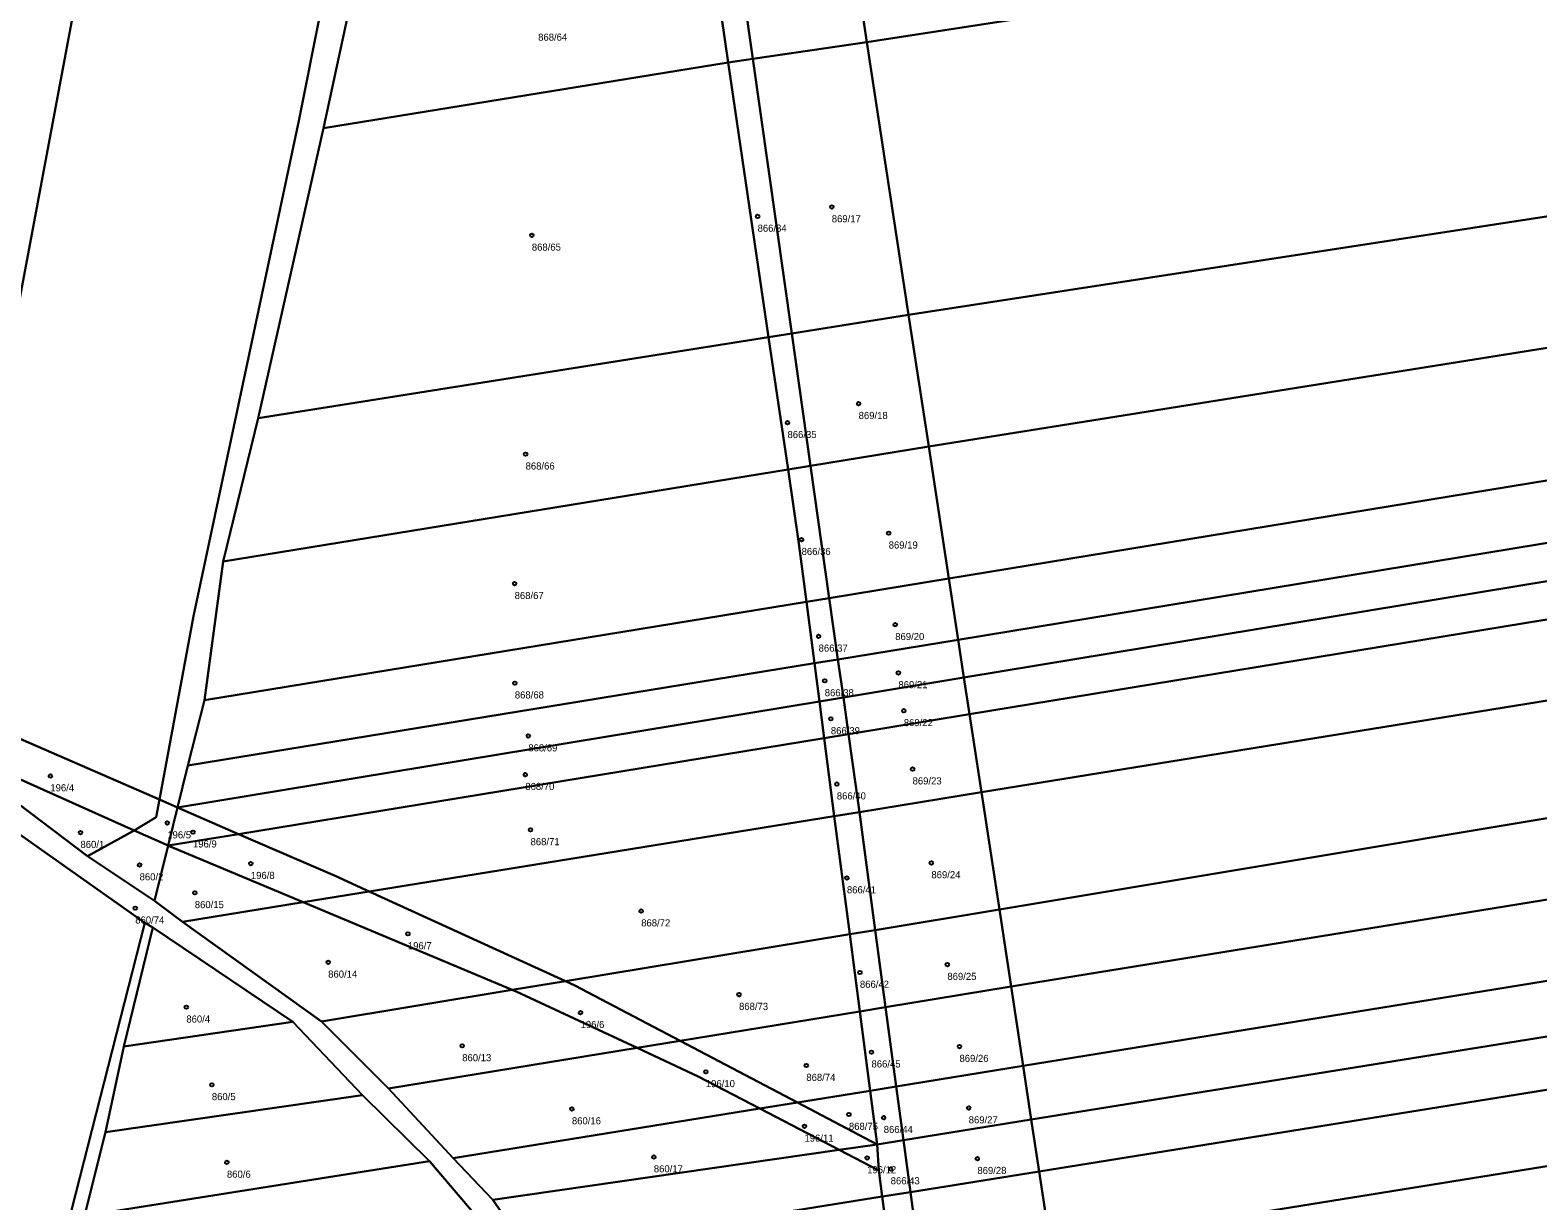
# Model space of a CAD drawing. Extents: x -587171 to -555306, y -1167727 to -1074732.
# Drawn here: x -584940 to -584727.9, y -1165439.3 to -1165274.5 of the extents above; entities that cross this region are included whole.
import ezdxf

# ---------------------------------------------------------------- set-up
doc = ezdxf.new("R2010")
doc.units = 0
doc.layers.add('Definiční body', color=7, linetype='Continuous')
doc.layers.add('Polygon parcely', color=7, linetype='Continuous')

msp = doc.modelspace()

# ---------------------------------------------------------------- linework, layer by layer
at = {"layer": 'Definiční body'}
for centre in [(-584827.22, -1165299.43), (-584837.66, -1165300.76), (-584869.43, -1165303.42), (-584823.44, -1165327.11), (-584833.45, -1165329.79), (-584870.31, -1165334.22), (-584831.47, -1165346.25), (-584819.21, -1165345.34), (-584871.85, -1165352.45), (-584818.29, -1165358.22), (-584829.07, -1165359.85), (-584828.21, -1165366.12), (-584817.84, -1165365), (-584871.82, -1165366.44), (-584817.08, -1165370.33), (-584827.35, -1165371.47), (-584869.93, -1165373.89), (-584815.85, -1165378.54), (-584937.19, -1165379.5), (-584870.35, -1165379.32), (-584826.51, -1165380.65), (-584920.73, -1165386.13), (-584869.61, -1165387.09), (-584932.95, -1165387.48), (-584917.12, -1165387.41), (-584924.63, -1165392.04), (-584908.97, -1165391.84), (-584813.2, -1165391.74), (-584825.09, -1165393.86), (-584916.86, -1165395.95), (-584925.24, -1165398.11), (-584854.04, -1165398.52), (-584886.87, -1165401.73), (-584898.09, -1165405.73), (-584810.95, -1165406.05), (-584823.26, -1165407.16), (-584840.27, -1165410.27), (-584918.05, -1165412.05), (-584862.57, -1165412.82), (-584879.23, -1165417.49), (-584821.63, -1165418.37), (-584809.25, -1165417.59), (-584844.94, -1165421.14), (-584830.8, -1165420.26), (-584914.46, -1165422.97), (-584863.79, -1165426.37), (-584824.81, -1165427.15), (-584819.91, -1165427.59), (-584807.95, -1165426.24), (-584831.06, -1165428.81), (-584912.34, -1165433.89), (-584852.26, -1165433.13), (-584822.24, -1165433.26), (-584806.73, -1165433.36), (-584818.93, -1165434.81)]:
    msp.add_circle(centre, 0.25, dxfattribs=at)
at = {"layer": 'Polygon parcely'}
for points in [[(-584893.49, -1165051.51), (-584911.55, -1165050.01), (-584941.09, -1165219.48), (-584966.57, -1165363.39), (-584952.29, -1165369.6), (-584925.66, -1165227.85), (-584895.33, -1165063.56)], [(-584902.21, -1165287.33), (-584883.81, -1165195.03), (-584866.02, -1165107.69), (-584871.7, -1165066.81), (-584877.29, -1165065.98), (-584895.33, -1165063.56), (-584925.66, -1165227.85), (-584952.29, -1165369.6), (-584921.83, -1165382.84), (-584917.06, -1165357.03)], [(-584891.42, -1165256.89), (-584889.07, -1165245.63), (-584885.14, -1165223.11), (-584881.74, -1165199.81), (-584875.97, -1165175.55), (-584870.48, -1165151.46), (-584864.44, -1165119), (-584865.05, -1165114.66), (-584866.02, -1165107.69), (-584883.81, -1165195.03), (-584902.21, -1165287.33), (-584917.06, -1165357.03), (-584921.83, -1165382.84), (-584919.3, -1165383.94), (-584917.84, -1165378.02), (-584915.49, -1165368.85), (-584912.89, -1165349.33), (-584907.92, -1165329.17), (-584898.75, -1165288.32), (-584894.3, -1165267.63)], [(-584351.89, -1165200.16), (-584365.79, -1165182.86), (-584489.27, -1165203.63), (-584611.49, -1165224.19), (-584718.07, -1165240.31), (-584825.25, -1165256.52), (-584822.27, -1165276.26), (-584720.86, -1165260.58), (-584619.2, -1165244.86), (-584486.44, -1165222.66)], [(-584323.29, -1165235.74), (-584351.89, -1165200.16), (-584486.44, -1165222.66), (-584619.2, -1165244.86), (-584720.86, -1165260.58), (-584822.27, -1165276.26), (-584816.4, -1165314.6), (-584703.23, -1165297.14), (-584589.9, -1165279.66), (-584445.07, -1165255.56)], [(-584310.41, -1165251.76), (-584323.29, -1165235.74), (-584445.07, -1165255.56), (-584589.9, -1165279.66), (-584703.23, -1165297.14), (-584816.4, -1165314.6), (-584813.57, -1165333.16), (-584703.91, -1165315.64), (-584594.47, -1165298.16), (-584433.81, -1165271.54)], [(-584297.99, -1165267.22), (-584310.41, -1165251.76), (-584433.81, -1165271.54), (-584594.47, -1165298.16), (-584703.91, -1165315.64), (-584813.57, -1165333.16), (-584810.74, -1165351.73), (-584697.98, -1165333.21), (-584585.84, -1165314.8), (-584423.32, -1165288.16)], [(-584822.27, -1165276.26), (-584825.25, -1165256.52), (-584841.12, -1165259.07), (-584838.35, -1165278.56)], [(-584841.78, -1165279.11), (-584844.63, -1165259.63), (-584894.3, -1165267.63), (-584898.75, -1165288.32)], [(-584841.78, -1165279.11), (-584838.35, -1165278.56), (-584841.12, -1165259.07), (-584844.63, -1165259.63)], [(-584291.06, -1165275.84), (-584297.99, -1165267.22), (-584423.32, -1165288.16), (-584585.84, -1165314.8), (-584697.98, -1165333.21), (-584810.74, -1165351.73), (-584809.43, -1165360.34), (-584694.26, -1165341.41), (-584579.59, -1165322.56), (-584417.2, -1165296.32)], [(-584816.4, -1165314.6), (-584822.27, -1165276.26), (-584838.35, -1165278.56), (-584832.86, -1165317.22)], [(-584287.34, -1165280.47), (-584291.06, -1165275.84), (-584417.2, -1165296.32), (-584579.59, -1165322.56), (-584694.26, -1165341.41), (-584809.43, -1165360.34), (-584808.62, -1165365.66), (-584694.75, -1165346.85), (-584581.15, -1165328.08), (-584416.04, -1165301.57)], [(-584836.12, -1165317.74), (-584832.86, -1165317.22), (-584838.35, -1165278.56), (-584841.78, -1165279.11)], [(-584836.12, -1165317.74), (-584841.78, -1165279.11), (-584898.75, -1165288.32), (-584907.92, -1165329.17)], [(-584283.55, -1165285.11), (-584284.55, -1165283.94), (-584287.34, -1165280.47), (-584416.04, -1165301.57), (-584581.15, -1165328.08), (-584694.75, -1165346.85), (-584808.62, -1165365.66), (-584807.83, -1165370.83), (-584692.25, -1165351.86), (-584577.37, -1165333.01), (-584418.95, -1165307.4)], [(-584274.66, -1165295.49), (-584283.55, -1165285.11), (-584418.95, -1165307.4), (-584577.37, -1165333.01), (-584692.25, -1165351.86), (-584807.83, -1165370.83), (-584806.16, -1165381.79), (-584689.43, -1165362.9), (-584572.61, -1165344), (-584411.37, -1165317.9)], [(-584262.29, -1165309.93), (-584274.66, -1165295.49), (-584411.37, -1165317.9), (-584572.61, -1165344), (-584689.43, -1165362.9), (-584806.16, -1165381.79), (-584803.64, -1165398.31), (-584684.63, -1165378.47), (-584566.14, -1165358.72), (-584403.21, -1165332.77)], [(-584253.65, -1165320.01), (-584262.29, -1165309.93), (-584403.21, -1165332.77), (-584566.14, -1165358.72), (-584684.63, -1165378.47), (-584803.64, -1165398.31), (-584801.99, -1165409.15), (-584685.41, -1165390.24), (-584569.1, -1165371.38), (-584400.01, -1165343.55)], [(-584813.57, -1165333.16), (-584816.4, -1165314.6), (-584832.86, -1165317.22), (-584830.21, -1165335.87)], [(-584833.38, -1165336.39), (-584836.12, -1165317.74), (-584907.92, -1165329.17), (-584912.89, -1165349.33)], [(-584832.86, -1165317.22), (-584836.12, -1165317.74), (-584833.38, -1165336.39), (-584830.21, -1165335.87)], [(-584245.68, -1165329.31), (-584253.65, -1165320.01), (-584400.01, -1165343.55), (-584569.1, -1165371.38), (-584685.41, -1165390.24), (-584801.99, -1165409.15), (-584800.29, -1165420.32), (-584679.97, -1165400.79), (-584559.08, -1165381.16), (-584392.72, -1165353.46)], [(-584240.53, -1165335.32), (-584245.68, -1165329.31), (-584392.72, -1165353.46), (-584559.08, -1165381.16), (-584679.97, -1165400.79), (-584800.29, -1165420.32), (-584799.14, -1165427.86), (-584679.59, -1165408.61), (-584558.94, -1165389.19), (-584384.85, -1165359.88)], [(-584810.74, -1165351.73), (-584813.57, -1165333.16), (-584830.21, -1165335.87), (-584827.57, -1165354.48)], [(-584830.21, -1165335.87), (-584833.38, -1165336.39), (-584831.86, -1165346.79), (-584830.79, -1165355.01), (-584827.57, -1165354.48)], [(-584234.7, -1165342.13), (-584240.53, -1165335.32), (-584384.85, -1165359.88), (-584558.94, -1165389.19), (-584679.59, -1165408.61), (-584799.14, -1165427.86), (-584798.03, -1165435.17), (-584677.37, -1165415.73), (-584556.85, -1165396.31), (-584382.81, -1165367.17)], [(-584830.79, -1165355.01), (-584831.86, -1165346.79), (-584833.38, -1165336.39), (-584912.89, -1165349.33), (-584915.49, -1165368.85)], [(-584225.63, -1165352.72), (-584234.7, -1165342.13), (-584382.81, -1165367.17), (-584556.85, -1165396.31), (-584677.37, -1165415.73), (-584798.03, -1165435.17), (-584796.43, -1165445.7), (-584675.02, -1165426.1), (-584553.98, -1165406.56), (-584379.31, -1165377.66)], [(-584809.43, -1165360.34), (-584810.74, -1165351.73), (-584827.57, -1165354.48), (-584826.35, -1165363.1)], [(-584214.53, -1165366.86), (-584221.82, -1165357.17), (-584225.63, -1165352.72), (-584379.31, -1165377.66), (-584553.98, -1165406.56), (-584675.02, -1165426.1), (-584796.43, -1165445.7), (-584794.03, -1165461.44), (-584670.52, -1165441.54), (-584547.57, -1165421.73), (-584380.19, -1165393.99)], [(-584829.67, -1165363.64), (-584830.79, -1165355.01), (-584915.49, -1165368.85), (-584917.84, -1165378.02)], [(-584829.67, -1165363.64), (-584826.35, -1165363.1), (-584827.57, -1165354.48), (-584830.79, -1165355.01)], [(-584808.62, -1165365.66), (-584809.43, -1165360.34), (-584826.35, -1165363.1), (-584825.59, -1165368.46)], [(-584828.97, -1165369.02), (-584829.67, -1165363.64), (-584917.84, -1165378.02), (-584919.3, -1165383.94)], [(-584825.59, -1165368.46), (-584826.35, -1165363.1), (-584829.67, -1165363.64), (-584828.97, -1165369.02)], [(-584807.83, -1165370.83), (-584808.62, -1165365.66), (-584825.59, -1165368.46), (-584824.86, -1165373.62)], [(-584953.66, -1165379.16), (-584971.92, -1165368.54), (-585005.85, -1165517.15), (-585002.31, -1165515.83), (-584997.11, -1165513.9), (-584991.97, -1165511.88), (-584986.52, -1165509.33), (-584981.47, -1165507.66), (-584976.27, -1165505.29), (-584971.31, -1165503.17), (-584966.14, -1165501.04), (-584961.72, -1165499.08), (-584956.22, -1165496.67), (-584951.29, -1165494.26), (-584947.38, -1165492.07), (-584923.91, -1165400.16)], [(-584922.29, -1165385.31), (-584921.83, -1165382.84), (-584952.29, -1165369.6), (-584953.26, -1165374.68), (-584925.4, -1165387.17)], [(-584828.3, -1165374.18), (-584828.97, -1165369.02), (-584919.3, -1165383.94), (-584910.71, -1165387.68)], [(-584825.59, -1165368.46), (-584828.97, -1165369.02), (-584828.3, -1165374.18), (-584824.86, -1165373.62)], [(-584806.16, -1165381.79), (-584807.83, -1165370.83), (-584824.86, -1165373.62), (-584823.34, -1165384.58)], [(-584826.87, -1165385.15), (-584828.3, -1165374.18), (-584910.71, -1165387.68), (-584897.13, -1165393.58), (-584892.33, -1165395.77)], [(-584826.87, -1165385.15), (-584823.34, -1165384.58), (-584824.86, -1165373.62), (-584828.3, -1165374.18)], [(-584931.98, -1165390.81), (-584925.4, -1165387.17), (-584953.26, -1165374.68)], [(-584920.63, -1165389.3), (-584919.3, -1165383.94), (-584921.83, -1165382.84), (-584922.29, -1165385.31), (-584925.4, -1165387.17)], [(-584803.64, -1165398.31), (-584806.16, -1165381.79), (-584823.34, -1165384.58), (-584821.11, -1165401.19)], [(-584919.3, -1165383.94), (-584920.63, -1165389.3), (-584910.71, -1165387.68)], [(-584823.34, -1165384.58), (-584826.87, -1165385.15), (-584824.7, -1165401.78), (-584821.11, -1165401.19)], [(-584824.7, -1165401.78), (-584826.87, -1165385.15), (-584892.33, -1165395.77), (-584864.69, -1165408.38)], [(-584931.98, -1165390.81), (-584922.55, -1165397.09), (-584920.63, -1165389.3), (-584925.4, -1165387.17)], [(-584901.63, -1165397.28), (-584892.33, -1165395.77), (-584897.13, -1165393.58), (-584910.71, -1165387.68), (-584920.63, -1165389.3), (-584920.32, -1165389.44)], [(-584918.6, -1165400.03), (-584901.63, -1165397.28), (-584920.32, -1165389.44), (-584920.63, -1165389.3), (-584922.55, -1165397.09)], [(-584899.05, -1165414.05), (-584872.2, -1165409.62), (-584901.63, -1165397.28), (-584918.6, -1165400.03)], [(-584892.33, -1165395.77), (-584901.63, -1165397.28), (-584872.2, -1165409.62), (-584864.69, -1165408.38)], [(-584801.99, -1165409.15), (-584803.64, -1165398.31), (-584821.11, -1165401.19), (-584819.65, -1165412.04)], [(-584936.62, -1165457.2), (-584932.39, -1165441.39), (-584929.45, -1165429.65), (-584926.85, -1165417.59), (-584922.77, -1165400.81), (-584923.91, -1165400.16), (-584947.38, -1165492.07), (-584944.94, -1165491.18), (-584939.72, -1165468.93)], [(-584903.08, -1165414.11), (-584922.77, -1165400.81), (-584926.85, -1165417.59)], [(-584823.29, -1165412.64), (-584824.7, -1165401.78), (-584864.69, -1165408.38), (-584863.37, -1165408.98), (-584848.55, -1165416.78)], [(-584821.11, -1165401.19), (-584824.7, -1165401.78), (-584823.29, -1165412.64), (-584819.65, -1165412.04)], [(-584889.6, -1165423.5), (-584854.63, -1165417.78), (-584871.62, -1165409.86), (-584872.2, -1165409.62), (-584899.05, -1165414.05)], [(-584864.69, -1165408.38), (-584872.2, -1165409.62), (-584871.62, -1165409.86), (-584854.63, -1165417.78), (-584848.55, -1165416.78), (-584863.37, -1165408.98)], [(-584800.29, -1165420.32), (-584801.99, -1165409.15), (-584819.65, -1165412.04), (-584818.15, -1165423.21)], [(-584821.83, -1165423.8), (-584818.15, -1165423.21), (-584819.65, -1165412.04), (-584823.29, -1165412.64)], [(-584903.08, -1165414.11), (-584926.85, -1165417.59), (-584929.45, -1165429.65), (-584893.28, -1165424.44)], [(-584821.83, -1165423.8), (-584823.29, -1165412.64), (-584848.55, -1165416.78), (-584832.06, -1165425.45)], [(-584846.02, -1165421.79), (-584837.35, -1165426.31), (-584832.06, -1165425.45), (-584848.55, -1165416.78), (-584854.63, -1165417.78)], [(-584837.35, -1165426.31), (-584846.02, -1165421.79), (-584854.63, -1165417.78), (-584889.6, -1165423.5), (-584880.48, -1165433.28)], [(-584799.14, -1165427.86), (-584800.29, -1165420.32), (-584818.15, -1165423.21), (-584817.14, -1165430.75)], [(-584818.15, -1165423.21), (-584821.83, -1165423.8), (-584820.85, -1165431.35), (-584817.14, -1165430.75)], [(-584883.83, -1165433.73), (-584893.28, -1165424.44), (-584929.45, -1165429.65), (-584932.39, -1165441.39)], [(-584832.06, -1165425.45), (-584820.85, -1165431.35), (-584821.83, -1165423.8)], [(-584874.94, -1165439.14), (-584826.19, -1165432.12), (-584837.35, -1165426.31), (-584880.48, -1165433.28)], [(-584826.19, -1165432.12), (-584820.85, -1165431.35), (-584832.06, -1165425.45), (-584837.35, -1165426.31)], [(-584798.03, -1165435.17), (-584799.14, -1165427.86), (-584817.14, -1165430.75), (-584816.16, -1165438.07)], [(-584820.6, -1165435.03), (-584820.85, -1165431.35), (-584826.19, -1165432.12)], [(-584817.14, -1165430.75), (-584820.85, -1165431.35), (-584820.6, -1165435.03), (-584820.11, -1165438.7), (-584816.16, -1165438.07)], [(-584883.83, -1165433.73), (-584932.39, -1165441.39), (-584936.62, -1165457.2), (-584872.59, -1165446.93)], [(-584869.72, -1165446.64), (-584820.11, -1165438.7), (-584820.6, -1165435.03), (-584826.19, -1165432.12), (-584874.94, -1165439.14)], [(-584796.43, -1165445.7), (-584798.03, -1165435.17), (-584816.16, -1165438.07), (-584814.75, -1165448.62)], [(-584814.75, -1165448.62), (-584816.16, -1165438.07), (-584820.11, -1165438.7), (-584818.7, -1165449.25)], [(-584818.7, -1165449.25), (-584820.11, -1165438.7), (-584869.72, -1165446.64), (-584861.58, -1165456.09)]]:
    msp.add_lwpolyline(points, close=True, dxfattribs=at)
for points in [[(-584869.72, -1165446.64), (-584874.94, -1165439.14), (-584880.48, -1165433.28), (-584889.6, -1165423.5), (-584899.05, -1165414.05), (-584918.6, -1165400.03), (-584922.55, -1165397.09), (-584931.98, -1165390.81), (-584953.26, -1165374.68)], [(-584953.66, -1165379.16), (-584923.91, -1165400.16), (-584922.77, -1165400.81), (-584903.08, -1165414.11), (-584893.28, -1165424.44), (-584883.83, -1165433.73), (-584872.59, -1165446.93)]]:
    msp.add_lwpolyline(points, dxfattribs=at)

# ---------------------------------------------------------------- texts
at = {"layer": 'Definiční body'}
for s, p in [('868/64', (-584868.54, -1165276.03)), ('866/34', (-584837.66, -1165302.92)), ('869/17', (-584827.22, -1165301.59)), ('868/65', (-584869.43, -1165305.58)), ('869/18', (-584823.44, -1165329.27)), ('866/35', (-584833.45, -1165331.95)), ('868/66', (-584870.31, -1165336.38)), ('869/19', (-584819.21, -1165347.5)), ('866/36', (-584831.47, -1165348.41)), ('868/67', (-584871.85, -1165354.61)), ('869/20', (-584818.29, -1165360.38)), ('866/37', (-584829.07, -1165362.01)), ('868/68', (-584871.82, -1165368.6)), ('866/38', (-584828.21, -1165368.28)), ('869/21', (-584817.84, -1165367.16)), ('869/22', (-584817.08, -1165372.49)), ('866/39', (-584827.35, -1165373.63)), ('868/69', (-584869.93, -1165376.05)), ('196/4', (-584937.19, -1165381.66)), ('868/70', (-584870.35, -1165381.48)), ('869/23', (-584815.85, -1165380.7)), ('866/40', (-584826.51, -1165382.81)), ('860/1', (-584932.95, -1165389.64)), ('196/5', (-584920.73, -1165388.29)), ('196/9', (-584917.12, -1165389.57)), ('868/71', (-584869.61, -1165389.25)), ('860/2', (-584924.63, -1165394.2)), ('196/8', (-584908.97, -1165394)), ('869/24', (-584813.2, -1165393.9)), ('866/41', (-584825.09, -1165396.02)), ('860/15', (-584916.86, -1165398.11)), ('860/74', (-584925.24, -1165400.27)), ('868/72', (-584854.04, -1165400.68)), ('196/7', (-584886.87, -1165403.89)), ('860/14', (-584898.09, -1165407.89)), ('866/42', (-584823.26, -1165409.32)), ('869/25', (-584810.95, -1165408.21)), ('868/73', (-584840.27, -1165412.43)), ('860/4', (-584918.05, -1165414.21)), ('196/6', (-584862.57, -1165414.98)), ('860/13', (-584879.23, -1165419.65)), ('869/26', (-584809.25, -1165419.75)), ('866/45', (-584821.63, -1165420.53)), ('196/10', (-584844.94, -1165423.3)), ('868/74', (-584830.8, -1165422.42)), ('860/5', (-584914.46, -1165425.13)), ('869/27', (-584807.95, -1165428.4)), ('860/16', (-584863.79, -1165428.53)), ('868/75', (-584824.81, -1165429.31)), ('866/44', (-584819.91, -1165429.75)), ('196/11', (-584831.06, -1165430.97)), ('860/6', (-584912.34, -1165436.05)), ('860/17', (-584852.26, -1165435.29)), ('196/12', (-584822.24, -1165435.42)), ('866/43', (-584818.93, -1165436.97)), ('869/28', (-584806.73, -1165435.52))]:
    msp.add_text(s, height=1, dxfattribs=at).set_placement(p)

doc.saveas('drawing.dxf')
